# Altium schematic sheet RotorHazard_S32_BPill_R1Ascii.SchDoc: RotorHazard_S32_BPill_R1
size C; DrawnBy: bduris; Engineer: bduris; Revision: 0.1; SheetNumber: 1; SheetTotal: 1; PageSetup: Record=PageOptions¦CenterHorizontal=True¦CenterVertical=True¦PrintScale=0.54¦XCorrection=1.00¦YCorrection=1.00¦PrintKind=0¦BorderSize=5000000¦LeftOffset=0¦BottomOffset=0¦Orientation=2¦PaperLength=1000¦PaperWidth=1000¦Scale=100¦PaperSource=15¦PrintQuality=-3¦MediaType=1¦DitherType=10¦PrintScaleMode=1¦PaperKind=Letter 8.5"x11" 22x28cm¦PaperIndex=1
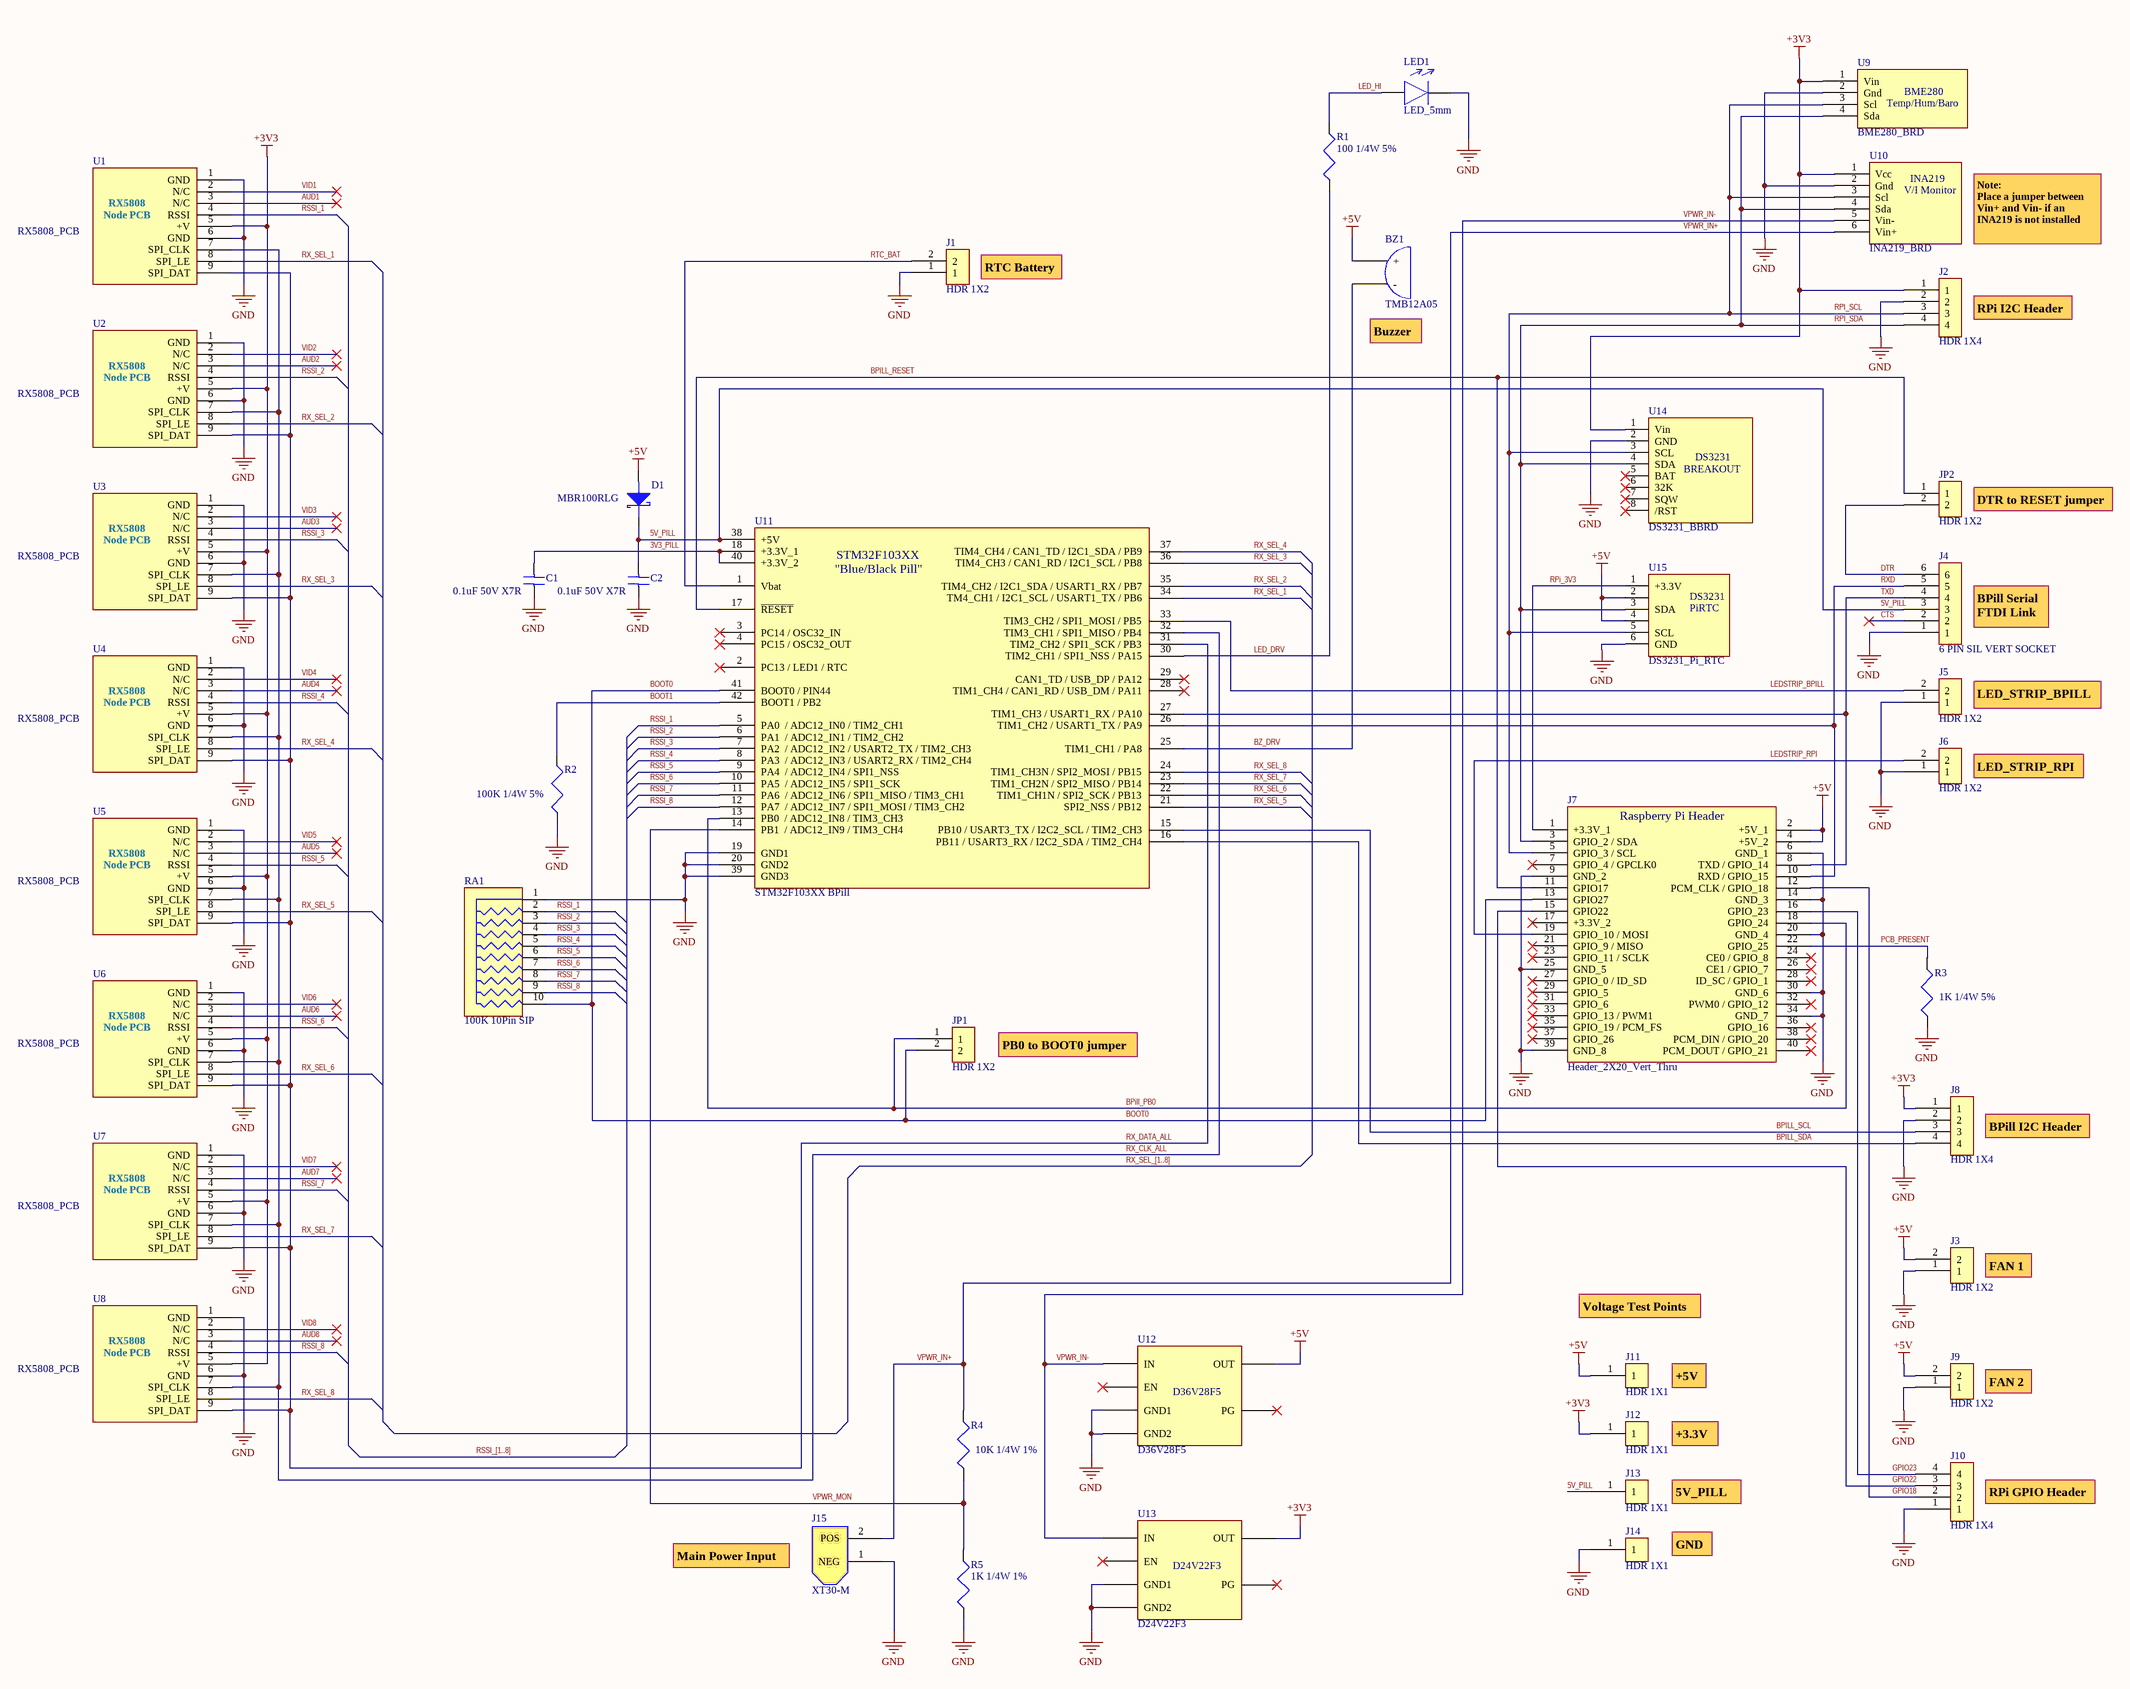
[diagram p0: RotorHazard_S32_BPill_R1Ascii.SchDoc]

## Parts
BZ1  TMB12A05  [BZ_12mm]
C1  0.1uF 50V X7R  [Cap Radial 100mil]
C2  0.1uF 50V X7R  [Cap Radial 100mil]
D1  MBR100RLG  [Axial 0.4 Diode]
J1  HDR 1X2  [HDR 1x2_2.54mm]
J2  HDR 1X4  [HDR 1x4_2.54mm]
J3  HDR 1X2  [HDR 1x2_2.54mm]
J4  6 PIN SIL VERT SOCKET  [6-PIN SIL VERT SOCKET]
J5  HDR 1X2  [HDR 1x2_2.54mm]
J6  HDR 1X2  [HDR 1x2_2.54mm]
J7  Header_2X20_Vert_Thru  [Header_2X20_Vert_Thru]
J8  HDR 1X4  [HDR 1x4_2.54mm]
J9  HDR 1X2  [HDR 1x2_2.54mm]
J10  HDR 1X4  [HDR 1x4_2.54mm]
J11  HDR 1X1  [HDR 1x1_2.54mm]
J12  HDR 1X1  [HDR 1x1_2.54mm]
J13  HDR 1X1  [HDR 1x1_2.54mm]
J14  HDR 1X1  [HDR 1x1_2.54mm]
J15  XT30-M  [XT30_M]
JP1  HDR 1X2  [HDR 1x2_2.54mm]
JP2  HDR 1X2  [HDR 1x2_2.54mm]
LED1  LED_5mm  [LED_5mm]
R1  100 1/4W 5%  [Axial 0.4 100 CF]
R2  100K 1/4W 5%  [Axial 0.4 100K CF]
R3  1K 1/4W 5%  [Axial 0.4 1K CF]
R4  10K 1/4W 1%  [Axial 0.4 10K MF]
R5  1K 1/4W 1%  [Axial 0.4 1K MF]
RA1  100K 10Pin SIP  [RES_SIP_10P]
U1  RX5808_PCB  [RH_S32_Node_PCB]
U2  RX5808_PCB  [RH_S32_Node_PCB]
U3  RX5808_PCB  [RH_S32_Node_PCB]
U4  RX5808_PCB  [RH_S32_Node_PCB]
U5  RX5808_PCB  [RH_S32_Node_PCB]
U6  RX5808_PCB  [RH_S32_Node_PCB]
U7  RX5808_PCB  [RH_S32_Node_PCB]
U8  RX5808_PCB  [RH_S32_Node_PCB]
U9  BME280_BRD  [BME280_PCB]
U10  INA219_BRD  [INA219_PCB_RA]
U11  STM32F103XX BPill  [DIP40_Plus2]
U12  D36V28F5  [D36V28FX]
U13  D24V22F3  [D24V22FX]
U14  DS3231_BBRD  [DS3231_Breakout]
U15  DS3231_Pi_RTC  [Pi_RTC]

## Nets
+3V3: J2.1 J8.1 J12.1 U1.5(+V) U2.5(+V) U3.5(+V) U4.5(+V) U5.5(+V) U6.5(+V) U7.5(+V) U8.5(+V) U9.1(Vin) U10.1(Vcc) U13.5(OUT) U14.1(Vin)
+5V: BZ1.2(+) D1.A(Anode) J3.2 J7.2(+5V_1) J7.4(+5V_2) J9.2 J11.1 U12.5(OUT) U15.2(N/C) U15.4(N/C)
GND: C1.1 C2.1 J1.1 J2.2 J3.1 J4.1 J5.1 J6.1 J7.6(GND_1) J7.9(GND_2) J7.14(GND_3) J7.20(GND_4) J7.25(GND_5) J7.30(GND_6) J7.34(GND_7) J7.39(GND_8) J8.2 J9.1 J10.1 J14.1 J15.1(NEG) LED1.K R2.1 R3.1 R5.1 RA1.1 U1.1(GND) U1.6(GND) U2.1(GND) U2.6(GND) U3.1(GND) U3.6(GND) U4.1(GND) U4.6(GND) U5.1(GND) U5.6(GND) U6.1(GND) U6.6(GND) U7.1(GND) U7.6(GND) U8.1(GND) U8.6(GND) U9.2(Gnd) U10.2(Gnd) U11.19(GND1) U11.20(GND2) U11.39(GND3) U12.3(GND1) U12.4(GND2) U13.4(GND1) U13.6(GND2) U14.2(GND) U15.6(GND)
3V3_PILL: C1.2 U11.18(+3.3V_1) U11.40(+3.3V_2)
5V_PILL: C2.2 D1.K(Cathode) J4.3 J13.1 U11.38(+5V)
AUD1: U1.3(N/C)
AUD2: U2.3(N/C)
AUD3: U3.3(N/C)
AUD4: U4.3(N/C)
AUD5: U5.3(N/C)
AUD6: U6.3(N/C)
AUD7: U7.3(N/C)
AUD8: U8.3(N/C)
BOOT0: J7.13(GPIO27) JP1.2 RA1.10 U11.41(BOOT0_/_PIN44)
BOOT1: R2.2 U11.42(BOOT1_/_PB2)
BPill_PB0: J7.18(GPIO_24) JP1.1 U11.13(PB0__/_ADC12_IN8_/_TIM3_CH3)
BPILL_RESET: J7.11(GPIO17) JP2.1 U11.17(~{RESET})
BPILL_SCL: J8.3 U11.15(PB10_/_USART3_TX_/_I2C2_SCL_/_TIM2_CH3)
BPILL_SDA: J8.4 U11.16(PB11_/_USART3_RX_/_I2C2_SDA_/_TIM2_CH4)
BZ_DRV: BZ1.1(-) U11.25(TIM1_CH1_/_PA8)
CTS: J4.2
DTR: J4.6 JP2.2
GPIO18: J7.12(PCM_CLK_/_GPIO_18) J10.2
GPIO22: J7.15(GPIO22) J10.3
GPIO23: J7.16(GPIO_23) J10.4
LED_DRV: R1.2 U11.30(TIM2_CH1_/_SPI1_NSS_/_PA15)
LED_HI: LED1.A R1.1
LEDSTRIP_BPILL: J5.2 U11.33(TIM3_CH2_/_SPI1_MOSI_/_PB5)
LEDSTRIP_RPI: J6.2 J7.19(GPIO_10_/_MOSI)
PCB_PRESENT: J7.22(GPIO_25) R3.2
RPi_3V3: J7.1(+3.3V_1) U15.1(+3.3V)
RPI_SCL: J2.3 J7.5(GPIO_3_/_SCL) U9.3(Scl) U10.3(Scl) U14.3(SCL) U15.5(SCL)
RPI_SDA: J2.4 J7.3(GPIO_2_/_SDA) U9.4(Sda) U10.4(Sda) U14.4(SDA) U15.3(SDA)
RSSI_1: RA1.2 U1.4(RSSI) U11.5(PA0__/_ADC12_IN0_/_TIM2_CH1)
RSSI_2: RA1.3 U2.4(RSSI) U11.6(PA1__/_ADC12_IN1_/_TIM2_CH2)
RSSI_3: RA1.4 U3.4(RSSI) U11.7(PA2__/_ADC12_IN2_/_USART2_TX_/_TIM2_CH3)
RSSI_4: RA1.5 U4.4(RSSI) U11.8(PA3__/_ADC12_IN3_/_USART2_RX_/_TIM2_CH4)
RSSI_5: RA1.6 U5.4(RSSI) U11.9(PA4__/_ADC12_IN4_/_SPI1_NSS)
RSSI_6: RA1.7 U6.4(RSSI) U11.10(PA5__/_ADC12_IN5_/_SPI1_SCK)
RSSI_7: RA1.8 U7.4(RSSI) U11.11(PA6__/_ADC12_IN6_/_SPI1_MISO_/_TIM3_CH1)
RSSI_8: RA1.9 U8.4(RSSI) U11.12(PA7__/_ADC12_IN7_/_SPI1_MOSI_/_TIM3_CH2)
RTC_BAT: J1.2 U11.1(Vbat)
RX_CLK_ALL: U1.7(SPI_CLK) U2.7(SPI_CLK) U3.7(SPI_CLK) U4.7(SPI_CLK) U5.7(SPI_CLK) U6.7(SPI_CLK) U7.7(SPI_CLK) U8.7(SPI_CLK) U11.32(TIM3_CH1_/_SPI1_MISO_/_PB4)
RX_DATA_ALL: U1.9(SPI_DAT) U2.9(SPI_DAT) U3.9(SPI_DAT) U4.9(SPI_DAT) U5.9(SPI_DAT) U6.9(SPI_DAT) U7.9(SPI_DAT) U8.9(SPI_DAT) U11.31(TIM2_CH2_/_SPI1_SCK_/_PB3)
RX_SEL_1: U1.8(SPI_LE) U11.34(TM4_CH1_/_I2C1_SCL_/_USART1_TX_/_PB6)
RX_SEL_2: U2.8(SPI_LE) U11.35(TIM4_CH2_/_I2C1_SDA_/_USART1_RX_/_PB7)
RX_SEL_3: U3.8(SPI_LE) U11.36(TIM4_CH3_/_CAN1_RD_/_I2C1_SCL_/_PB8)
RX_SEL_4: U4.8(SPI_LE) U11.37(TIM4_CH4_/_CAN1_TD_/_I2C1_SDA_/_PB9)
RX_SEL_5: U5.8(SPI_LE) U11.21(SPI2_NSS_/_PB12)
RX_SEL_6: U6.8(SPI_LE) U11.22(TIM1_CH1N_/_SPI2_SCK_/_PB13)
RX_SEL_7: U7.8(SPI_LE) U11.23(TIM1_CH2N_/_SPI2_MISO_/_PB14)
RX_SEL_8: U8.8(SPI_LE) U11.24(TIM1_CH3N_/_SPI2_MOSI_/_PB15)
RXD: J4.5 J7.10(RXD_/_GPIO_15) U11.26(TIM1_CH2_/_USART1_TX_/_PA9)
TXD: J4.4 J7.8(TXD_/_GPIO_14) U11.27(TIM1_CH3_/_USART1_RX_/_PA10)
VID1: U1.2(N/C)
VID2: U2.2(N/C)
VID3: U3.2(N/C)
VID4: U4.2(N/C)
VID5: U5.2(N/C)
VID6: U6.2(N/C)
VID7: U7.2(N/C)
VID8: U8.2(N/C)
VPWR_IN+: J15.2(POS) R4.2 U10.6(Vin+)
VPWR_IN-: U10.5(Vin-) U12.2(IN) U13.3(IN)
VPWR_MON: R4.1 R5.2 U11.14(PB1__/_ADC12_IN9_/_TIM3_CH4)

Not connected (* = marked no-connect by the designer): J7 7(GPIO_4_/_GPCLK0)* 17(+3.3V_2)* 21(GPIO_9_/_MISO)* 23(GPIO_11_/_SCLK)* 24(CE0_/_GPIO_8)* 26(CE1_/_GPIO_7)* 27(GPIO_0_/_ID_SD)* 28(ID_SC_/_GPIO_1)* 29(GPIO_5)* 31(GPIO_6)* 32(PWM0_/_GPIO_12)* 33(GPIO_13_/_PWM1)* 35(GPIO_19_/_PCM_FS)* 36(GPIO_16)* 37(GPIO_26)* 38(PCM_DIN_/_GPIO_20)* 40(PCM_DOUT_/_GPIO_21)*; U11 2(PC13_/_LED1_/_RTC)* 3(PC14_/_OSC32_IN)* 4(PC15_/_OSC32_OUT)* 28(TIM1_CH4_/_CAN1_RD_/_USB_DM_/_PA11)* 29(CAN1_TD_/_USB_DP_/_PA12)*; U12 1(EN)* 6(PG)*; U13 1(PG)* 2(EN)*; U14 5(BAT)* 6(32K)* 7(SQW)* 8(/RST)*

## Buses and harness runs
bus RSSI_[1..8]
bus RX_SEL_[1..8]

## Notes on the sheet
- Note:
  Place a jumper between
  Vin+ and Vin- if an
  INA219 is not installed
- (near J1) RTC Battery
- (near BZ1) Buzzer
- (near J2) RPi I2C Header
- (near JP2) DTR to RESET jumper
- (near J4) BPill Serial
  FTDI Link
- (near J5) LED_STRIP_BPILL
- (near J6) LED_STRIP_RPI
- PB0 to BOOT0 jumper
- (near J8) BPill I2C Header
- (near J3) FAN 1
- Voltage Test Points
- +5V
- (near J9) FAN 2
- +3.3V
- 5V_PILL
- (near J10) RPi GPIO Header
- Main Power Input
- GND

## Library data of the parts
BZ1 = Buzzer_12mm: TMB12A05 12mmX9.5mm Buzzer
C1 C2 = C320C104K5R5TA7301: Multilayer Ceramic Capacitors MLCC - Leaded 50V 0.1uF 10% X7R; Manufacturer: KEMET; Type: Radial Leads; Voltage Rating DC: 50 VDC; Case Style: Conformally Coated; Capacitance - nF: 100 nF; Capacitance - pF: 100000 pF; Dissipation Factor DF: 2.5; Lead Diameter: 0.51 mm
D1 = MBR1100RLG: Schottky Diodes & Rectifiers 1A 100V; Manufacturer: ON Semiconductor; Configuration: Single; Ifsm - Forward Surge Current: 50 A; Ir - Reverse Current: 500 uA; Vf - Forward Voltage: 0.79 V
J1 J3 J5 J6 J9 JP1 JP2 = 961102-6804-AR: Headers & Wire Housings 2P STRT 1 ROW GOLD 6.8MM MATING PIN; Manufacturer: 3M Electronic Solutions Division; Current Rating: 2 A; Mounting Angle: Straight; Number of Positions: 2 Position; Pitch: 2.54 mm; Latching Type: Unlatched
J2 J8 J10 = 961104-6804-AR: Headers & Wire Housings 4P STRT 1 ROW GOLD 6.8MM MATING PIN; Manufacturer: 3M Electronic Solutions Division; Current Rating: 2 A; Mounting Angle: Straight; Number of Positions: 4 Position; Pitch: 2.54 mm; Latching Type: Unlatched
J4 = M20-7820646: Headers & Wire Housings 6 PIN SIL VERTICAL SOCKET TIN; Manufacturer: Harwin; Number of Contacts: 6; Max Current Rating: 3A; Contact Resistance: 20mR; Connector Type: Receptacle,Socket; Gender: Female; Pitch: 2.54mm
J7 = Header_To_Pi_Cable: Manufacturer: Harwin; Manufacturer Part Number: M50-3552042; Current Rating: 1.75 A; Mounting Angle: Straight; Number of Positions: 40 Position; Pitch: 1.27 mm; Insulation Resistance: 5000 MOhms; Latching Type: Eject Latch; Mating Post Length: 3.05 mm
J11-J14 = HEADER 1X1: Single pin header
J15 = XT30-M: XT30 connector male pins
LED1 = LED_5mm: 5mm standard leaded red LED
R1 = CFR-25JR-52-100R: Carbon Film Resistors - Through Hole 100ohm 1/4W 5%; Manufacturer: Yageo; Power Rating: 250 mW (1/4 W); Resistance: 100 Ohms; Temperature Coefficient: 350 PPM / C; Voltage Rating: 250 V; Lead Diameter: 0.55 mm
R2 = CFR-25JR-52-100K: Carbon Film Resistors - Through Hole 100K ohm 1/4W 5%; Manufacturer: Yageo; Power Rating: 250 mW (1/4 W); Resistance: 100 kOhms; Temperature Coefficient: 350 PPM / C; Voltage Rating: 250 V; Lead Diameter: 0.55 mm
R3 = CFR-25JT-52-1K: Carbon Film Resistors - Through Hole 1/4W 1K Ohm 5%; Manufacturer: Yageo; Power Rating: 250 mW (1/4 W); Resistance: 1 kOhms; Temperature Coefficient: - 350 PPM / C, 500 PPM / C; Voltage Rating: 250 V; Lead Diameter: 0.55 mm
R4 = MFR-25FRF52-10K: Metal Film Resistors - Through Hole 10K ohm 1/4W 1%; Manufacturer: Yageo; Power Rating: 250 mW (1/4 W); Resistance: 10 kOhms; Temperature Coefficient: 100 PPM / C; Voltage Rating: 250 V; Lead Diameter: 0.6 mm
R5 = MFR-25FRF52-1K: Metal Film Resistors - Through Hole 1K ohm 1/4W 1%; Manufacturer: Yageo; Power Rating: 250 mW (1/4 W); Resistance: 1 kOhms; Temperature Coefficient: 100 PPM / C; Voltage Rating: 250 V; Lead Diameter: 0.6 mm
RA1 = 4610X-101-104LF: Resistor Networks & Arrays 10pins 100Kohms Bussed; Manufacturer: Bourns; Temperature Coefficient: 100 PPM / C; Tolerance: 2 %; Voltage Rating: 100 V; Number of Resistors: 9; Lead Diameter: 0.508 mm; Power per Element: 125 mW (1/8 W); Power Total Package: 1.13 W
U1-U8 = RH_S32_Node: RX5808 module on PCB with right-angle header pins
U9 = BME280: BME280 Temperature, Humidity and Pressure Sensor
U10 = INA219_BRD: INA219 Current Sensor/Voltage Monitor
U11 = STM32F103XX_BPill: STMF103XX BPill
U12 = D36V28F5: Pololu D36V28F5 DC/DC Converter
U13 = D24V22F3: Pololu D24V22F3 DC/DC Converter
U14 = DS3231_Breakout: ADAFruit DS3231 Breakout Board
U15 = DS3231_Pi_RTC: ADAFruit DS3231 PiRTC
